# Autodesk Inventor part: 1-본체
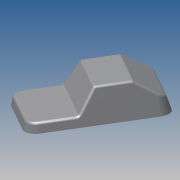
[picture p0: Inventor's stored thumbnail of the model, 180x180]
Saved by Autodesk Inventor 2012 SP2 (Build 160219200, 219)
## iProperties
Created: 2015-05
Part Number: 1-본체
Material: Default
Document SubType Name: Modeling
Designer: Administrator
Density: 1 g/cm^3
Author: Administrator
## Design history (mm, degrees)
sketch "스케치2"
  geometry: L1 (-49, 38)-(49, 38); L2 (61, 26)-(61, -26); L3 (49, -38)-(-49, -38); L4 (-61, -26)-(-61, 26); A1 r 12 centre (-49, 26) between (-49, 38) and (-61, 26); A2 r 12 centre (-49, -26) between (-61, -26) and (-49, -38); A3 r 12 centre (49, -26) between (49, -38) and (61, -26); A4 r 12 centre (49, 26) between (61, 26) and (49, 38); 6 further points
  constraints: 8 end point, 8 point on circle, 8 tangent, 6 point on line, 4 centre point, 3 equal radius, 2 midpoint, 2 parallel, 1 horizontal, 1 horizontal alignment, 1 perpendicular, 1 vertical alignment
  dimensions: "d13" = 122 distance of point (-61, 38) point (61, 38); "d14" = 76 distance of point (-61, -38) point (-61, 38); "d15" = 12 radius of A1
extrude "돌출1" new body sketch "스케치2" distance "d16" = 31; taper "d17" = -15 deg
sketch "스케치3"
  geometry: L1 (-52.694, 31)-(-49, 31) reference; L2 (-49, 0)-(-49, 31) reference; L3 (-49, 0)-(-61, 0) reference; L4 (-61, 0)-(-52.694, 31) reference; L5 (-49, 31)-(49, 31) reference; L6 (49, 0)-(49, 31) reference; L7 (49, 0)-(-49, 0) reference; L8 (-49, 0)-(-49, 31) reference; L9 (49, 31)-(52.694, 31) reference; L10 (61, 0)-(52.694, 31) reference; L11 (61, 0)-(49, 0) reference; L12 (49, 0)-(49, 31) reference; L13 (-58.588, 9)-(-16.588, 9); L14 (-16.588, 9)-(-1.184, 31); L15 (31, 31)-(57.412, 13.392); L16 (61, 0)-(61, 11); L17 (57.412, 13.392)-(61, 11); L18 (-1.184, 31)-(-52.694, 31); L19 (-58.588, 9)-(-52.694, 31); L20 (31, 31)-(52.694, 31); L21 (52.694, 31)-(57.412, 13.392); 1 further point
  constraints: 18 end point, 5 collinear, 4 point on line, 2 perpendicular
  dimensions: "d18" = 9 vertical distance of L13.start L3.end; "d19" = 42 distance of L13.start L13.end; "d20" = 125 deg angle of L14 L13; "d21" = 30 horizontal distance of L15.start L10.start; "d23" = 11 distance of L10.start L16.end
extrude "돌출2" cut sketch "스케치3" stored distance "d24" = 31; taper "d25" = 0 deg
fillet "모깎기1" dims "d26" = 3
fillet "모깎기2" dims "d27" = 3
feature "쉘1" dims "d42" = 2
node "솔리드1"
node "투영된 루프1"
node "투영된 루프2"
node "투영된 루프3"
